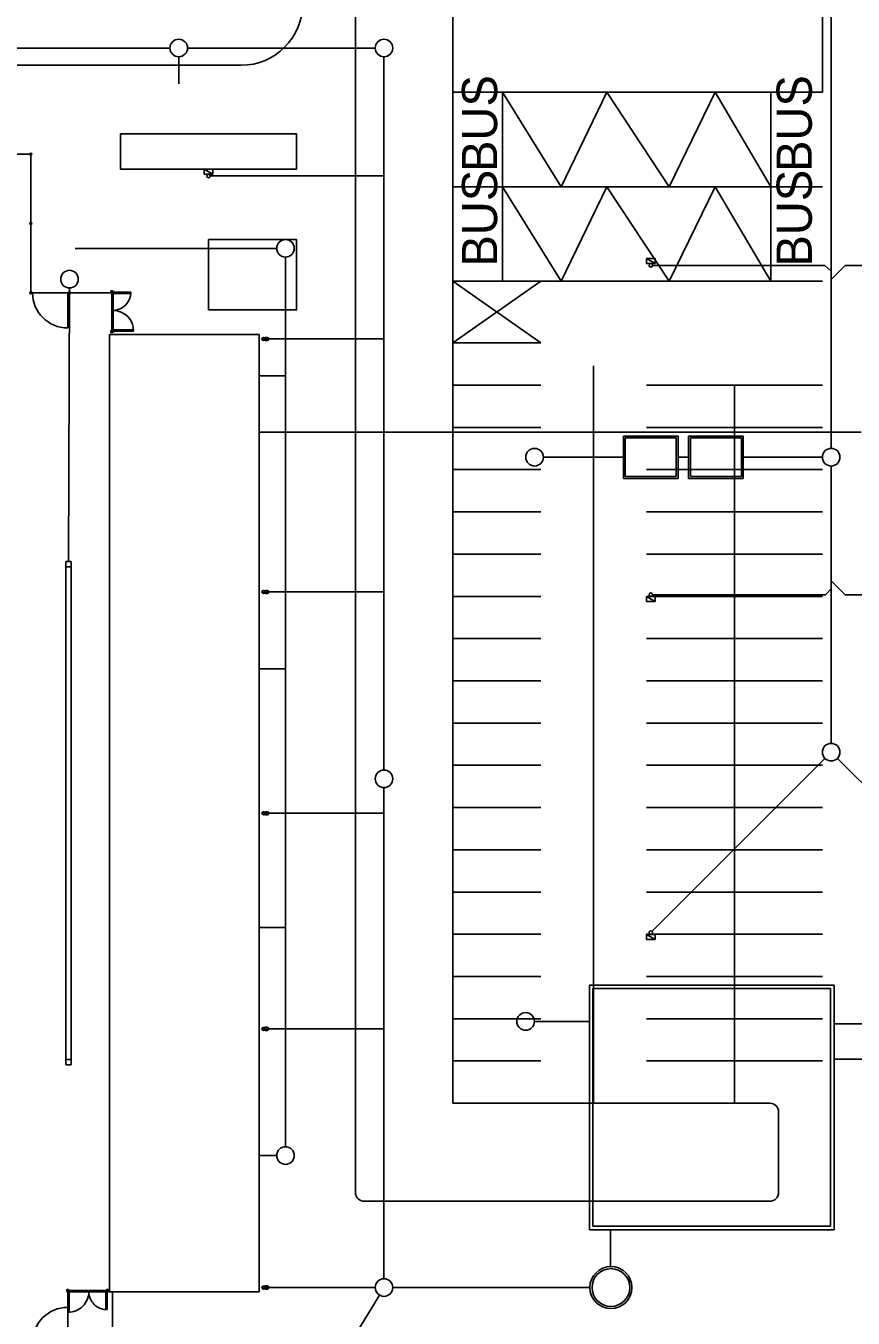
# Model space of a CAD drawing. Extents: x -264205 to -263615, y -1242401 to -1242031.
# Drawn here: x -263972.3 to -263925.3, y -1242253.7 to -1242180.2 of the extents above; entities that cross this region are included whole.
import ezdxf

# ---------------------------------------------------------------- set-up
doc = ezdxf.new("R2010")
doc.units = 0
doc.layers.add('KOORDINACNA_SITUACIA_DSP', color=7, linetype='Continuous')
doc.layers.add('PROJEKT_DRS_TDZ_VODOROVNE', color=7, linetype='Continuous')

msp = doc.modelspace()

# ---------------------------------------------------------------- linework, layer by layer
at = {"layer": 'KOORDINACNA_SITUACIA_DSP'}
for p, q in [((-263948.093, -1242087.901), (-263948.093, -1242241.458)), ((-263953.617, -1242244.458), (-263953.617, -1242093.307)), ((-263926.593, -1242155.252), (-263926.593, -1242204.252)), ((-264013.161, -1242181.5), (-263964.161, -1242181.5)), ((-263963.661, -1242182), (-263963.661, -1242183.528)), ((-263963.161, -1242181.5), (-263952.5, -1242181.5)), ((-263952, -1242222.527), (-263952, -1242182)), ((-263960.118, -1242182.482), (-264034.158, -1242182.482)), ((-263972.068, -1242187.532), (-264118.068, -1242187.532)), ((-263972.128, -1242187.532), (-263972.008, -1242187.532)), ((-263972.068, -1242187.592), (-263972.068, -1242187.472)), ((-263972.068, -1242195.407), (-263972.068, -1242187.532)), ((-263962.218, -1242188.382), (-263961.718, -1242188.382)), ((-263962.218, -1242188.672), (-263962.218, -1242188.382)), ((-263962.218, -1242188.382), (-263961.718, -1242188.672)), ((-263962.218, -1242188.382), (-263961.718, -1242188.672)), ((-263961.718, -1242188.382), (-263962.218, -1242188.382)), ((-263961.718, -1242188.672), (-263962.218, -1242188.672)), ((-263961.718, -1242188.382), (-263961.718, -1242188.672)), ((-263961.718, -1242188.672), (-263961.718, -1242188.382)), ((-263961.868, -1242188.772), (-263952, -1242188.772)), ((-263972.128, -1242191.47), (-263972.008, -1242191.47)), ((-263972.068, -1242191.41), (-263972.068, -1242191.53)), ((-263958.097, -1242192.883), (-263969.542, -1242192.883)), ((-263957.597, -1242243.932), (-263957.597, -1242193.383)), ((-263937.093, -1242193.752), (-263937.093, -1242193.462)), ((-263937.093, -1242193.462), (-263936.593, -1242193.462)), ((-263936.593, -1242193.752), (-263937.093, -1242193.462)), ((-263936.593, -1242193.752), (-263937.093, -1242193.462)), ((-263937.093, -1242193.462), (-263937.093, -1242193.752)), ((-263936.593, -1242193.752), (-263937.093, -1242193.752)), ((-263937.093, -1242193.752), (-263936.593, -1242193.752)), ((-263936.743, -1242193.852), (-263926.953, -1242193.852)), ((-263936.593, -1242193.462), (-263936.593, -1242193.752)), ((-263926.953, -1242193.852), (-263926.593, -1242194.178)), ((-263925.798, -1242193.852), (-263926.593, -1242194.648)), ((-263920.944, -1242193.852), (-263925.798, -1242193.852)), ((-263969.921, -1242210.683), (-263969.869, -1242195.133)), ((-263967.413, -1242195.307), (-263967.513, -1242195.307)), ((-263967.513, -1242195.307), (-263967.513, -1242195.407)), ((-263967.425, -1242195.32), (-263967.5, -1242195.32)), ((-263967.5, -1242195.32), (-263967.5, -1242195.395)), ((-263967.425, -1242195.395), (-263967.425, -1242195.32)), ((-263967.425, -1242195.395), (-263967.425, -1242195.345)), ((-263967.425, -1242195.345), (-263967.325, -1242195.345)), ((-263967.413, -1242195.407), (-263967.413, -1242195.307)), ((-263967.413, -1242195.357), (-263967.363, -1242195.357)), ((-263967.363, -1242195.357), (-263967.363, -1242195.457)), ((-263967.325, -1242195.345), (-263967.325, -1242195.37)), ((-263972.068, -1242195.407), (-263967.418, -1242195.407)), ((-263969.968, -1242195.407), (-263969.968, -1242197.407)), ((-263967.513, -1242195.407), (-263967.413, -1242195.407)), ((-263967.5, -1242195.395), (-263967.425, -1242195.395)), ((-263967.463, -1242195.407), (-263967.463, -1242196.395)), ((-263967.388, -1242195.407), (-263967.463, -1242195.407)), ((-263967.388, -1242196.395), (-263967.388, -1242195.407)), ((-263967.363, -1242195.457), (-263967.388, -1242195.457)), ((-263966.388, -1242195.371), (-263967.375, -1242195.37)), ((-263967.375, -1242195.37), (-263967.375, -1242195.445)), ((-263967.375, -1242195.445), (-263966.388, -1242195.446)), ((-263967.463, -1242197.557), (-263967.463, -1242196.42)), ((-263967.388, -1242196.42), (-263967.388, -1242197.557)), ((-263967.513, -1242197.557), (-263967.413, -1242197.557)), ((-263967.513, -1242197.657), (-263967.513, -1242197.557)), ((-263967.388, -1242197.557), (-263967.463, -1242197.557)), ((-263967.413, -1242197.557), (-263967.413, -1242197.657)), ((-263967.363, -1242197.507), (-263967.388, -1242197.507)), ((-263967.375, -1242197.52), (-263966.238, -1242197.52)), ((-263967.375, -1242197.595), (-263967.375, -1242197.52)), ((-263967.363, -1242197.607), (-263967.363, -1242197.507)), ((-263967.593, -1242252.182), (-263967.593, -1242197.782)), ((-263967.593, -1242197.782), (-263959.093, -1242197.782)), ((-263967.593, -1242197.782), (-263959.097, -1242197.782)), ((-263967.593, -1242252.182), (-263967.593, -1242197.782)), ((-263967.413, -1242197.657), (-263967.513, -1242197.657)), ((-263967.5, -1242197.57), (-263967.425, -1242197.57)), ((-263967.5, -1242197.645), (-263967.5, -1242197.57)), ((-263967.425, -1242197.645), (-263967.5, -1242197.645)), ((-263967.478, -1242197.782), (-263967.358, -1242197.782)), ((-263967.425, -1242197.57), (-263967.425, -1242197.62)), ((-263967.425, -1242197.57), (-263967.425, -1242197.645)), ((-263967.425, -1242197.62), (-263967.325, -1242197.62)), ((-263967.413, -1242197.607), (-263967.363, -1242197.607)), ((-263966.238, -1242197.595), (-263967.375, -1242197.595)), ((-263967.325, -1242197.62), (-263967.325, -1242197.595)), ((-263959.097, -1242197.782), (-263959.093, -1242252.182)), ((-263959.093, -1242197.782), (-263959.093, -1242252.182)), ((-263958.799, -1242197.962), (-263958.762, -1242197.962)), ((-263958.799, -1242198.102), (-263958.762, -1242198.102)), ((-263958.762, -1242197.962), (-263958.742, -1242197.942)), ((-263958.762, -1242198.102), (-263958.742, -1242198.122)), ((-263958.742, -1242197.942), (-263958.637, -1242197.942)), ((-263958.742, -1242198.122), (-263958.637, -1242198.122)), ((-263958.575, -1242198.032), (-263952, -1242198.032)), ((-263959.097, -1242200.132), (-263957.597, -1242200.132)), ((-263959.097, -1242203.332), (-263958.097, -1242203.332)), ((-263924.893, -1242203.332), (-263958.097, -1242203.332)), ((-263938.393, -1242203.552), (-263935.293, -1242203.552)), ((-263938.393, -1242205.952), (-263938.393, -1242203.552)), ((-263938.293, -1242205.852), (-263938.293, -1242203.652)), ((-263938.293, -1242203.652), (-263935.393, -1242203.652)), ((-263935.393, -1242205.852), (-263935.393, -1242203.652)), ((-263935.293, -1242205.952), (-263935.293, -1242203.552)), ((-263934.693, -1242203.552), (-263931.593, -1242203.552)), ((-263934.693, -1242203.552), (-263934.693, -1242205.952)), ((-263934.593, -1242203.652), (-263934.593, -1242205.852)), ((-263934.593, -1242203.652), (-263931.693, -1242203.652)), ((-263931.693, -1242203.652), (-263931.693, -1242205.852)), ((-263931.593, -1242203.552), (-263931.593, -1242205.952)), ((-263938.393, -1242204.752), (-263942.945, -1242204.752)), ((-263934.693, -1242204.752), (-263935.293, -1242204.752)), ((-263927.093, -1242204.752), (-263931.593, -1242204.752)), ((-263926.593, -1242221.011), (-263926.593, -1242205.252)), ((-263935.293, -1242205.952), (-263938.393, -1242205.952)), ((-263935.393, -1242205.852), (-263938.293, -1242205.852)), ((-263931.593, -1242205.952), (-263934.693, -1242205.952)), ((-263931.693, -1242205.852), (-263934.593, -1242205.852)), ((-263970.071, -1242210.684), (-263969.77, -1242210.682)), ((-263970.07, -1242239.282), (-263970.071, -1242210.684)), ((-263969.77, -1242210.682), (-263969.77, -1242239.282)), ((-263970.071, -1242210.983), (-263969.771, -1242210.985)), ((-263926.919, -1242212.562), (-263926.593, -1242212.237)), ((-263925.798, -1242212.562), (-263926.593, -1242211.767)), ((-263958.799, -1242212.337), (-263958.762, -1242212.337)), ((-263958.799, -1242212.477), (-263958.762, -1242212.477)), ((-263958.762, -1242212.337), (-263958.742, -1242212.317)), ((-263958.762, -1242212.477), (-263958.742, -1242212.497)), ((-263958.742, -1242212.317), (-263958.637, -1242212.317)), ((-263958.742, -1242212.497), (-263958.637, -1242212.497)), ((-263958.575, -1242212.407), (-263952, -1242212.407)), ((-263937.093, -1242212.952), (-263937.093, -1242212.662)), ((-263937.093, -1242212.662), (-263936.593, -1242212.662)), ((-263936.593, -1242212.952), (-263937.093, -1242212.662)), ((-263936.593, -1242212.952), (-263937.093, -1242212.662)), ((-263937.093, -1242212.662), (-263937.093, -1242212.952)), ((-263936.593, -1242212.952), (-263937.093, -1242212.952)), ((-263937.093, -1242212.952), (-263936.593, -1242212.952)), ((-263936.743, -1242212.562), (-263926.919, -1242212.562)), ((-263936.593, -1242212.662), (-263936.593, -1242212.952)), ((-263916.443, -1242212.562), (-263925.798, -1242212.562)), ((-263959.097, -1242216.782), (-263957.597, -1242216.782)), ((-263936.772, -1242231.691), (-263926.947, -1242221.865)), ((-263916.414, -1242231.691), (-263926.24, -1242221.865)), ((-263952, -1242251.432), (-263952, -1242223.527)), ((-263958.799, -1242224.912), (-263958.762, -1242224.912)), ((-263958.799, -1242225.052), (-263958.762, -1242225.052)), ((-263958.762, -1242224.912), (-263958.742, -1242224.892)), ((-263958.762, -1242225.052), (-263958.742, -1242225.072)), ((-263958.742, -1242224.892), (-263958.637, -1242224.892)), ((-263958.742, -1242225.072), (-263958.637, -1242225.072)), ((-263958.575, -1242224.982), (-263952, -1242224.982)), ((-263959.097, -1242231.482), (-263957.597, -1242231.482)), ((-263937.093, -1242231.862), (-263936.593, -1242231.862)), ((-263937.093, -1242232.152), (-263937.093, -1242231.862)), ((-263937.093, -1242231.862), (-263936.593, -1242232.152)), ((-263937.093, -1242231.862), (-263936.593, -1242232.152)), ((-263936.593, -1242231.862), (-263937.093, -1242231.862)), ((-263936.593, -1242231.862), (-263936.593, -1242232.152)), ((-263936.593, -1242232.152), (-263936.593, -1242231.862)), ((-263936.593, -1242232.152), (-263937.093, -1242232.152)), ((-263926.43, -1242234.749), (-263940.33, -1242234.749)), ((-263940.33, -1242234.749), (-263940.33, -1242248.649)), ((-263926.63, -1242234.949), (-263940.13, -1242234.949)), ((-263940.13, -1242234.949), (-263940.13, -1242248.449)), ((-263926.63, -1242248.449), (-263926.63, -1242234.949)), ((-263926.43, -1242248.649), (-263926.43, -1242234.749)), ((-263958.799, -1242237.162), (-263958.762, -1242237.162)), ((-263958.762, -1242237.162), (-263958.742, -1242237.142)), ((-263958.742, -1242237.142), (-263958.637, -1242237.142)), ((-263940.33, -1242236.811), (-263943.454, -1242236.811)), ((-263919.13, -1242236.949), (-263926.43, -1242236.949)), ((-263958.799, -1242237.302), (-263958.762, -1242237.302)), ((-263958.762, -1242237.302), (-263958.742, -1242237.322)), ((-263958.742, -1242237.322), (-263958.637, -1242237.322)), ((-263958.575, -1242237.232), (-263952, -1242237.232)), ((-263969.77, -1242238.982), (-263970.07, -1242238.982)), ((-263969.77, -1242239.282), (-263970.07, -1242239.282)), ((-263907.219, -1242238.949), (-263926.43, -1242238.949)), ((-263930.081, -1242241.458), (-263948.093, -1242241.458)), ((-263929.582, -1242246.53), (-263929.581, -1242241.959)), ((-263959.097, -1242244.432), (-263958.097, -1242244.432)), ((-263953.617, -1242244.458), (-263953.619, -1242246.529)), ((-263953.119, -1242247.03), (-263930.082, -1242247.03)), ((-263940.33, -1242248.649), (-263926.43, -1242248.649)), ((-263940.13, -1242248.449), (-263926.63, -1242248.449)), ((-263939.13, -1242248.649), (-263939.13, -1242250.737)), ((-263958.799, -1242251.862), (-263958.762, -1242251.862)), ((-263958.762, -1242251.862), (-263958.742, -1242251.842)), ((-263958.742, -1242251.842), (-263958.637, -1242251.842)), ((-263970.018, -1242252.152), (-263970.018, -1242252.052)), ((-263970.018, -1242252.052), (-263969.918, -1242252.052)), ((-263969.918, -1242252.152), (-263970.018, -1242252.152)), ((-263970.005, -1242252.14), (-263970.005, -1242252.065)), ((-263970.005, -1242252.065), (-263969.93, -1242252.065)), ((-263969.93, -1242252.14), (-263970.005, -1242252.14)), ((-263969.93, -1242252.14), (-263969.98, -1242252.14)), ((-263969.98, -1242252.14), (-263969.98, -1242252.24)), ((-263969.98, -1242252.24), (-263969.955, -1242252.24)), ((-263969.968, -1242252.152), (-263969.968, -1242252.202)), ((-263969.968, -1242252.202), (-263969.868, -1242252.202)), ((-263969.955, -1242253.327), (-263969.955, -1242252.19)), ((-263969.955, -1242252.19), (-263969.88, -1242252.19)), ((-263969.93, -1242252.065), (-263969.93, -1242252.14)), ((-263969.918, -1242252.052), (-263969.918, -1242252.152)), ((-263969.918, -1242252.102), (-263968.78, -1242252.102)), ((-263969.918, -1242252.177), (-263969.918, -1242252.102)), ((-263968.78, -1242252.177), (-263969.918, -1242252.177)), ((-263969.88, -1242252.19), (-263969.88, -1242253.327)), ((-263969.868, -1242252.202), (-263969.868, -1242252.177)), ((-263968.78, -1242252.102), (-263968.78, -1242252.177)), ((-263967.768, -1242252.102), (-263968.755, -1242252.102)), ((-263968.755, -1242252.102), (-263968.755, -1242252.177)), ((-263968.755, -1242252.177), (-263967.768, -1242252.177)), ((-263967.818, -1242252.202), (-263967.818, -1242252.177)), ((-263967.718, -1242252.202), (-263967.818, -1242252.202)), ((-263967.805, -1242252.19), (-263967.807, -1242253.177)), ((-263967.73, -1242252.19), (-263967.805, -1242252.19)), ((-263967.768, -1242252.152), (-263967.768, -1242252.052)), ((-263967.768, -1242252.052), (-263967.668, -1242252.052)), ((-263967.768, -1242252.177), (-263967.768, -1242252.102)), ((-263967.668, -1242252.152), (-263967.768, -1242252.152)), ((-263967.755, -1242252.14), (-263967.755, -1242252.065)), ((-263967.755, -1242252.065), (-263967.68, -1242252.065)), ((-263967.755, -1242252.14), (-263967.705, -1242252.14)), ((-263967.68, -1242252.14), (-263967.755, -1242252.14)), ((-263967.732, -1242253.177), (-263967.73, -1242252.19)), ((-263967.705, -1242252.24), (-263967.73, -1242252.24)), ((-263967.718, -1242252.152), (-263967.718, -1242252.202)), ((-263967.705, -1242252.14), (-263967.705, -1242252.24)), ((-263967.68, -1242252.065), (-263967.68, -1242252.14)), ((-263967.668, -1242252.052), (-263967.668, -1242252.152)), ((-263959.093, -1242252.182), (-263967.593, -1242252.182)), ((-263959.093, -1242252.182), (-263967.593, -1242252.182)), ((-263967.418, -1242252.182), (-263967.418, -1242255.057)), ((-263958.799, -1242252.002), (-263958.762, -1242252.002)), ((-263958.762, -1242252.002), (-263958.742, -1242252.022)), ((-263958.742, -1242252.022), (-263958.637, -1242252.022)), ((-263958.575, -1242251.932), (-263952.5, -1242251.932)), ((-263953.57, -1242254.506), (-263952.26, -1242252.359)), ((-263940.302, -1242251.932), (-263951.5, -1242251.932)), ((-263969.968, -1242255.057), (-263969.968, -1242253.057))]:
    msp.add_line(p, q, dxfattribs=at)
for points in [[(-263966.968, -1242186.382), (-263956.968, -1242186.382), (-263956.968, -1242188.382), (-263966.968, -1242188.382)], [(-263961.968, -1242192.382), (-263956.968, -1242192.382), (-263956.968, -1242196.382), (-263961.968, -1242196.382)], [(-263967.597, -1242197.782), (-263959.097, -1242197.782), (-263959.097, -1242252.182), (-263967.597, -1242252.182)]]:
    msp.add_lwpolyline(points, close=True, dxfattribs=at)
for centre, radius in [((-263963.661, -1242181.5), 0.5), ((-263952, -1242181.5), 0.5), ((-263972.068, -1242187.532), 0.06), ((-263961.968, -1242188.772), 0.1), ((-263972.068, -1242191.47), 0.06), ((-263957.597, -1242192.883), 0.5), ((-263936.843, -1242193.852), 0.1), ((-263969.868, -1242194.633), 0.5), ((-263972.068, -1242195.407), 0.06), ((-263969.868, -1242195.407), 0.06), ((-263958.847, -1242198.032), 0.085), ((-263958.847, -1242198.032), 0.0625), ((-263958.637, -1242198.032), 0.0625), ((-263943.445, -1242204.752), 0.5), ((-263926.593, -1242204.752), 0.5), ((-263958.847, -1242212.407), 0.085), ((-263958.847, -1242212.407), 0.0625), ((-263958.637, -1242212.407), 0.0625), ((-263936.843, -1242212.562), 0.1), ((-263926.593, -1242221.511), 0.5), ((-263952, -1242223.027), 0.5), ((-263958.847, -1242224.982), 0.085), ((-263958.847, -1242224.982), 0.0625), ((-263958.637, -1242224.982), 0.0625), ((-263936.843, -1242231.762), 0.1), ((-263943.954, -1242236.811), 0.5), ((-263958.847, -1242237.232), 0.085), ((-263958.847, -1242237.232), 0.0625), ((-263958.637, -1242237.232), 0.0625), ((-263957.597, -1242244.432), 0.5), ((-263939.107, -1242251.932), 1.195), ((-263939.107, -1242251.932), 1.075), ((-263958.847, -1242251.932), 0.085), ((-263958.847, -1242251.932), 0.0625), ((-263958.637, -1242251.932), 0.0625), ((-263952, -1242251.932), 0.5)]:
    msp.add_circle(centre, radius, dxfattribs=at)
for centre, radius, start, end in [((-263960.118, -1242178.982), 3.5, 270, 0), ((-263969.968, -1242195.407), 2, 180, 270), ((-263967.4, -1242195.382), 1.025, 270.60954, 0.60953), ((-263967.4, -1242197.582), 1.175, 359.39047, 89.39046), ((-263958.637, -1242198.032), 0.09, 270, 90), ((-263958.637, -1242212.407), 0.09, 270, 90), ((-263958.637, -1242224.982), 0.09, 270, 90), ((-263958.637, -1242237.232), 0.09, 270, 90), ((-263930.081, -1242241.958), 0.5, 359.97854, 89.99994), ((-263953.119, -1242246.53), 0.5, 179.95255, 270), ((-263930.082, -1242246.53), 0.5, 270, 359.97854), ((-263958.637, -1242251.932), 0.09, 270, 90), ((-263969.943, -1242252.165), 1.175, 269.39046, 359.39047), ((-263967.743, -1242252.165), 1.025, 180.60953, 270.60954), ((-263969.968, -1242255.057), 2, 90, 180)]:
    msp.add_arc(centre, radius, start, end, dxfattribs=at)
for centre in [(-263967.4, -1242195.382), (-263967.4, -1242195.382), (-263967.4, -1242197.582), (-263969.943, -1242252.165), (-263969.943, -1242252.165), (-263967.743, -1242252.165)]:
    msp.add_ellipse(centre, major_axis=(0, 0.0125), ratio=0.999995, dxfattribs=at)
at = {"layer": 'PROJEKT_DRS_TDZ_VODOROVNE'}
for p, q in [((-263945.265, -1242189.382), (-263945.265, -1242184.007)), ((-263930.029, -1242189.383), (-263930.029, -1242184.008)), ((-263948.093, -1242189.382), (-263927.093, -1242189.382)), ((-263945.263, -1242194.758), (-263945.263, -1242189.383)), ((-263930.027, -1242194.758), (-263930.027, -1242189.383)), ((-263948.093, -1242194.757), (-263927.093, -1242194.757)), ((-263943.093, -1242194.757), (-263948.093, -1242198.257)), ((-263943.093, -1242198.257), (-263948.093, -1242194.757)), ((-263948.093, -1242198.257), (-263943.093, -1242198.257)), ((-263940.088, -1242241.458), (-263940.09, -1242199.557)), ((-263948.093, -1242200.657), (-263943.093, -1242200.657)), ((-263937.093, -1242200.657), (-263932.093, -1242200.657)), ((-263932.093, -1242200.657), (-263932.093, -1242241.457)), ((-263927.093, -1242200.657), (-263932.093, -1242200.657)), ((-263948.093, -1242203.057), (-263943.093, -1242203.057)), ((-263937.093, -1242203.057), (-263932.093, -1242203.057)), ((-263927.093, -1242203.057), (-263932.093, -1242203.057)), ((-263948.093, -1242205.457), (-263943.093, -1242205.457)), ((-263937.093, -1242205.457), (-263932.093, -1242205.457)), ((-263927.093, -1242205.457), (-263932.093, -1242205.457)), ((-263948.093, -1242207.857), (-263943.093, -1242207.857)), ((-263937.093, -1242207.857), (-263932.093, -1242207.857)), ((-263927.093, -1242207.857), (-263932.093, -1242207.857)), ((-263948.093, -1242210.257), (-263943.093, -1242210.257)), ((-263937.093, -1242210.257), (-263932.093, -1242210.257)), ((-263927.093, -1242210.257), (-263932.093, -1242210.257)), ((-263948.093, -1242212.657), (-263943.093, -1242212.657)), ((-263937.093, -1242212.657), (-263932.093, -1242212.657)), ((-263927.093, -1242212.657), (-263932.093, -1242212.657)), ((-263948.093, -1242215.057), (-263943.093, -1242215.057)), ((-263937.093, -1242215.057), (-263932.093, -1242215.057)), ((-263927.093, -1242215.057), (-263932.093, -1242215.057)), ((-263948.093, -1242217.457), (-263943.093, -1242217.457)), ((-263937.093, -1242217.457), (-263932.093, -1242217.457)), ((-263927.093, -1242217.457), (-263932.093, -1242217.457)), ((-263948.093, -1242219.857), (-263943.093, -1242219.857)), ((-263937.093, -1242219.857), (-263932.093, -1242219.857)), ((-263927.093, -1242219.857), (-263932.093, -1242219.857)), ((-263948.093, -1242222.257), (-263943.093, -1242222.257)), ((-263937.093, -1242222.257), (-263932.093, -1242222.257)), ((-263927.093, -1242222.257), (-263932.093, -1242222.257)), ((-263948.093, -1242224.657), (-263943.093, -1242224.657)), ((-263937.093, -1242224.657), (-263932.093, -1242224.657)), ((-263927.093, -1242224.657), (-263932.093, -1242224.657)), ((-263948.093, -1242227.057), (-263943.093, -1242227.057)), ((-263937.093, -1242227.057), (-263932.093, -1242227.057)), ((-263927.093, -1242227.057), (-263932.093, -1242227.057)), ((-263948.093, -1242229.457), (-263943.093, -1242229.457)), ((-263937.093, -1242229.457), (-263932.093, -1242229.457)), ((-263927.093, -1242229.457), (-263932.093, -1242229.457)), ((-263948.093, -1242231.857), (-263943.093, -1242231.857)), ((-263937.093, -1242231.857), (-263932.093, -1242231.857)), ((-263927.093, -1242231.857), (-263932.093, -1242231.857)), ((-263948.093, -1242234.257), (-263943.093, -1242234.257)), ((-263937.093, -1242234.257), (-263932.093, -1242234.257)), ((-263927.093, -1242234.257), (-263932.093, -1242234.257)), ((-263948.093, -1242236.657), (-263943.093, -1242236.657)), ((-263937.093, -1242236.657), (-263932.093, -1242236.657)), ((-263927.093, -1242236.657), (-263932.093, -1242236.657)), ((-263948.093, -1242239.057), (-263943.093, -1242239.057)), ((-263937.093, -1242239.057), (-263932.093, -1242239.057)), ((-263927.093, -1242239.057), (-263932.093, -1242239.057))]:
    msp.add_line(p, q, dxfattribs=at)
for points in [[(-263927.093, -1242134.007), (-263948.093, -1242134.007), (-263948.093, -1242184.007), (-263927.093, -1242184.007), (-263927.093, -1242134.007)], [(-263945.265, -1242184.008), (-263941.938, -1242189.382), (-263939.333, -1242184.008), (-263935.8, -1242189.382), (-263933.192, -1242184.008), (-263930.029, -1242189.382)], [(-263945.263, -1242189.383), (-263941.936, -1242194.758), (-263939.331, -1242189.383), (-263935.798, -1242194.758), (-263933.19, -1242189.383), (-263930.027, -1242194.758)]]:
    msp.add_lwpolyline(points, dxfattribs=at)

# ---------------------------------------------------------------- texts
for p in [(-263945.572, -1242188.544), (-263927.694, -1242188.544), (-263945.57, -1242193.92), (-263927.692, -1242193.92)]:
    msp.add_text('BUS', height=2, rotation=90, dxfattribs=at).set_placement(p)

doc.saveas('drawing.dxf')
